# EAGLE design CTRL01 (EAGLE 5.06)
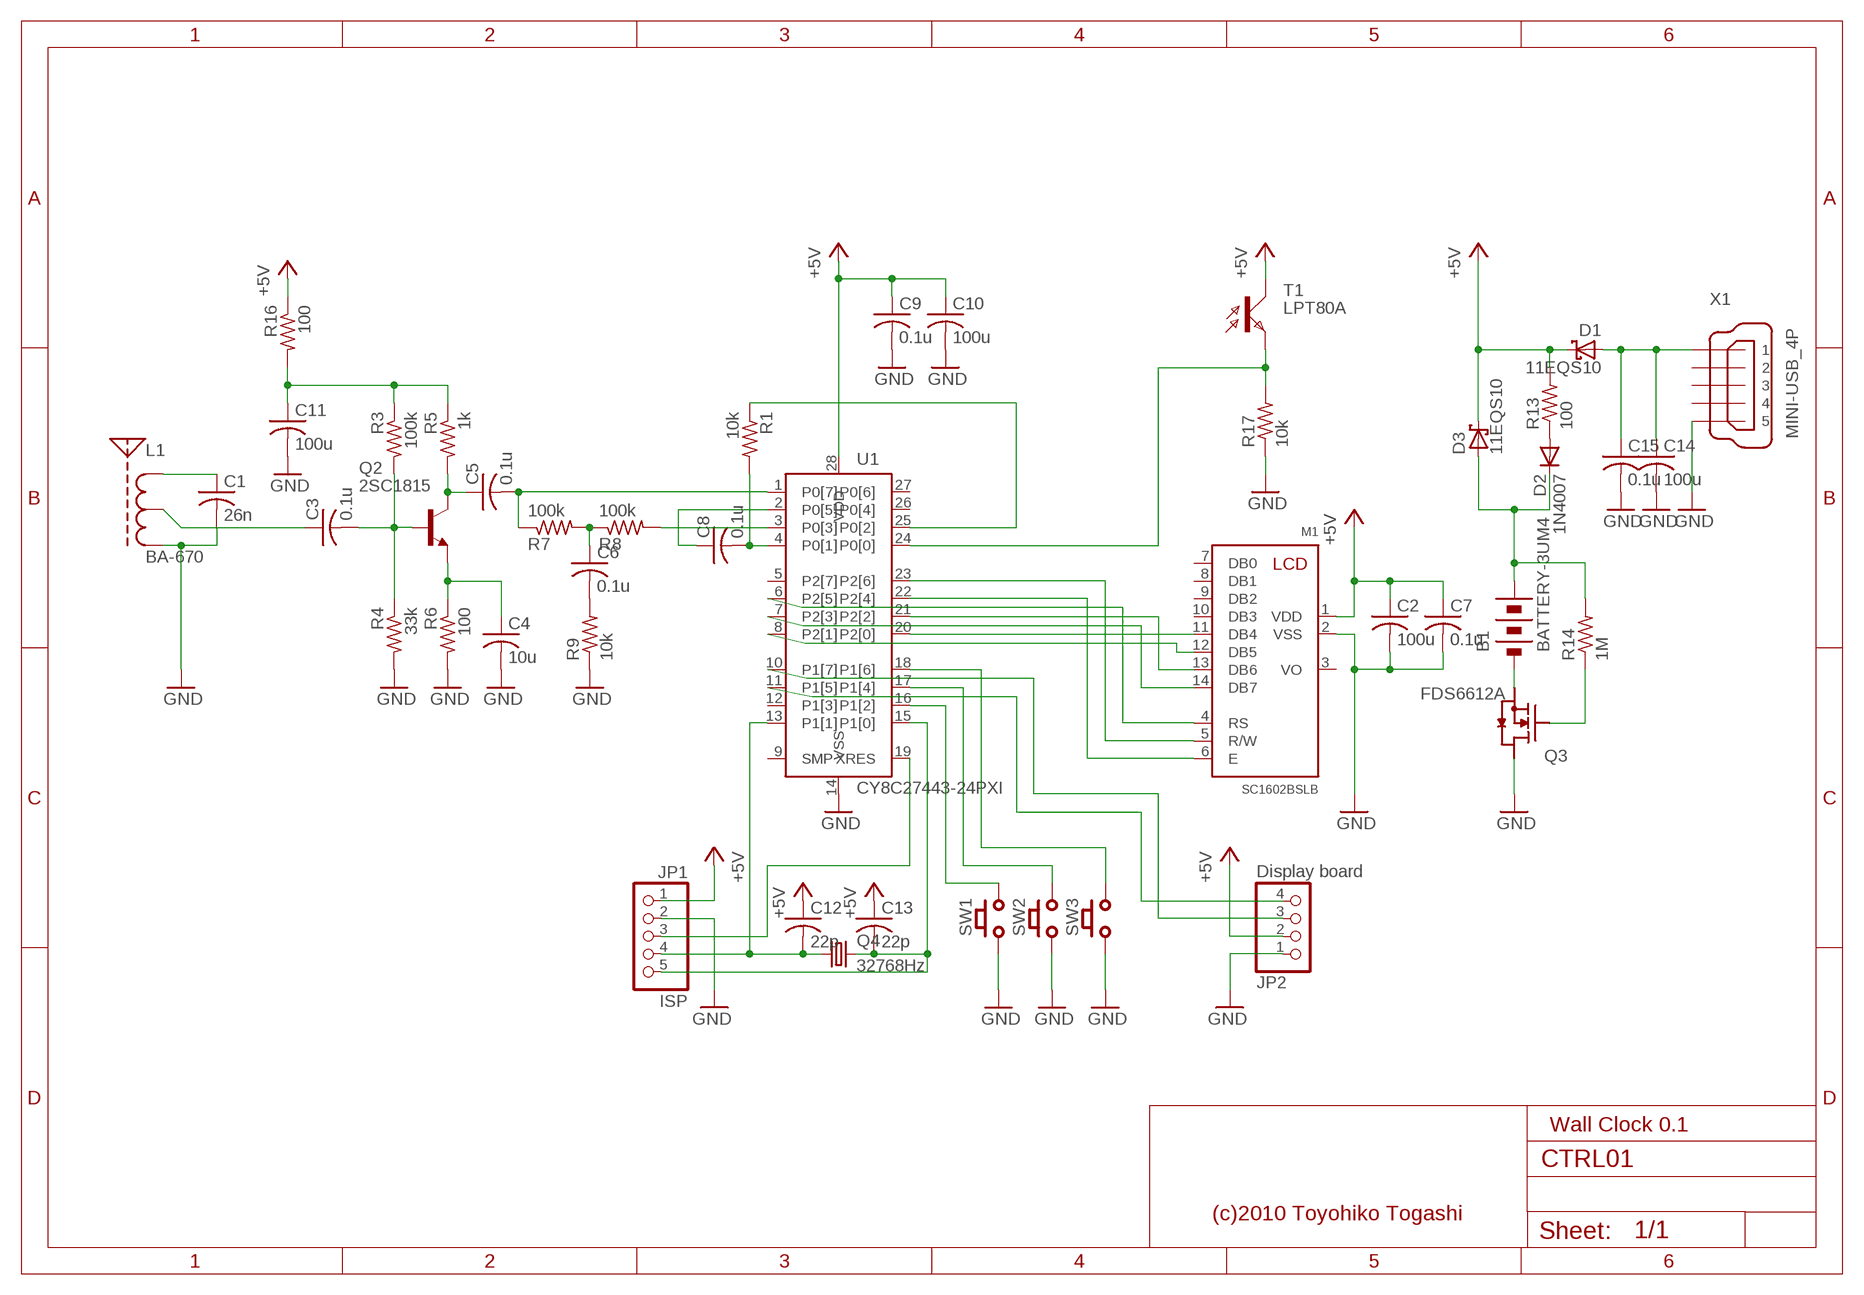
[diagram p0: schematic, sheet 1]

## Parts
B1  BATTERY-3UM4  [BATHLDR-UM4X3]
C1  26n  C-US025-024X044  [C025-024X044]
C2  100u  C-US025-024X044  [C025-024X044]
C3  0.1u  C-US025-024X044  [C025-024X044]
C4  10u  C-US025-024X044  [C025-024X044]
C5  0.1u  C-US050-025X075  [C050-025X075]
C6  0.1u  C-US025-024X044  [C025-024X044]
C7  0.1u  C-US025-024X044  [C025-024X044]
C8  0.1u  C-US025-024X044  [C025-024X044]
C9  0.1u  C-US025-024X044  [C025-024X044]
C10  100u  C-US025-024X044  [C025-024X044]
C11  100u  C-US025-024X044  [C025-024X044]
C12  22p  C-US025-024X044  [C025-024X044]
C13  22p  C-US025-024X044  [C025-024X044]
C14  100u  C-US025-024X044  [C025-024X044]
C15  0.1u  C-US025-024X044  [C025-024X044]
D1  11EQS10  SCHOTTKY-DIODEDO35-7  [DO35-7]
D2  1N4007  1N4148DO35-7  [DO35-7]
D3  11EQS10  SCHOTTKY-DIODEDO35-7  [DO35-7]
JP1  ISP  PINHD-1X5  [1X05]
JP2  Display board  PINHD-1X4  [1X04]
L1  BA-670  [BA-670]
M1  SC1602BSLB  [SC1602B]
Q2  2SC1815  [TO92-ECB]
Q3  FDS6612A  [SOP8]
Q4  32768Hz  CRYSTALTC26H  [TC26H]
R1  10k  R-US_0204/5  [0204/5]
R3  100k  R-US_0204/5  [0204/5]
R4  33k  R-US_0204/5  [0204/5]
R5  1k  R-US_0204/5  [0204/5]
R6  100  R-US_0204/5  [0204/5]
R7  100k  R-US_0204/5  [0204/5]
R8  100k  R-US_0204/5  [0204/5]
R9  10k  R-US_0204/5  [0204/5]
R13  100  R-US_0204/5  [0204/5]
R14  1M  R-US_0204/5  [0204/5]
R16  100  R-US_0204/5  [0204/5]
R17  10k  R-US_0204/5  [0204/5]
SW1  SWITCH-PUSH"  [SWITCH-PUSH]
SW2  SWITCH-PUSH"  [SWITCH-PUSH]
SW3  SWITCH-PUSH"  [SWITCH-PUSH]
T1  LPT80A  [LPT80A]
U1  CY8C27443-24PXI  [DIL28-3]
X1  MINI-USB_4P  AKI-USB-MINI-B  [AKI-USB-MINI-B]

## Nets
+5V: C2.1 C7.1 C9.1 C10.1 C12.1 C13.1 D1.C D3.C JP1.1 JP2.2 M1.1(VDD) R13.2 R16.1 T1.C U1.28(VDD)
N$1: C1.1 L1.NATURAL
N$2: C3.2 Q2.B R3.2 R4.1
N$3: C3.1 L1.BLACK
N$4: R8.2 U1.3(P0[3])
N$5: C4.1 Q2.E R6.1
N$6: C5.1 Q2.C R5.2
N$7: C8.1 U1.2(P0[5])
N$8: JP2.3 U1.10(P1[7])
N$9: C6.1 R7.2 R8.1
N$10: C6.2 R9.2
N$11: C8.2 R1.2 U1.4(P0[1])
N$12: R1.1 U1.25(P0[2])
N$13: C5.2 R7.1 U1.1(P0[7])
N$14: JP2.4 U1.11(P1[5])
N$17: M1.11(DB4) U1.20(P2[0])
N$18: M1.12(DB5) U1.8(P2[1])
N$19: M1.13(DB6) U1.21(P2[2])
N$20: M1.14(DB7) U1.7(P2[3])
N$21: M1.6(E) U1.22(P2[4])
N$22: M1.5(R/W) U1.23(P2[6])
N$23: M1.4(RS) U1.6(P2[5])
N$24: B1.P$2(MINUS) Q3.P$1(S)
N$25: D2.A R13.1
N$27: Q3.P$4(G) R14.1
N$28: B1.P$1(PLUS) D2.C D3.A R14.2
N$30: C11.1 R3.1 R5.1 R16.2
N$31: C12.2 JP1.4 Q4.1 U1.13(P1[1])
N$32: C13.2 JP1.5 Q4.2 U1.15(P1[0])
N$33: SW1.P$2(A2) U1.16(P1[2])
N$34: JP1.3 U1.19(XRES)
N$35: SW2.P$2(A2) U1.17(P1[4])
N$36: SW3.P$2(A2) U1.18(P1[6])
N$37: R17.2 T1.E U1.24(P0[0])
N$38: C14.1 C15.1 D1.A X1.1
N$39: C1.2 C2.2 C4.2 C7.2 C9.2 C10.2 C11.2 C14.2 C15.2 JP1.2 JP2.1 L1.GREEN M1.2(VSS) Q3.P$5(D) R4.2 R6.2 R9.1 R17.1 SW1.P$1(A1) SW2.P$1(A1) SW3.P$1(A1) U1.14(VSS) X1.5 ; supply symbol labelled GND
Unconnected: M1.3(VO) M1.7(DB0) M1.8(DB1) M1.9(DB2) M1.10(DB3) U1.5(P2[7]) U1.12(P1[3]) U1.26(P0[4]) U1.27(P0[6]) X1.2 X1.3 X1.4

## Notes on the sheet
- Wall Clock 0.1
- (c)2010 Toyohiko Togashi

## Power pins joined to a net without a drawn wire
SMP: U1.9(SMP)

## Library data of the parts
B1 = TOG:BATTERY-3: Battery 3cell
C1-C15 = rcl:C-US: CAPACITOR, American symbol
D1 D3 = diode:SCHOTTKY-DIODE: Schottky Diode
D2 = diode:1N4148: DIODE
JP1 = pinhead:PINHD-1X5: PIN HEADER
JP2 = pinhead:PINHD-1X4: PIN HEADER
L1 = TOG:BA-670: AIKO DENSHI MW band AM radio bar antenna 670uH +/-5% Q200~/790kHz 3x8x45mm
M1 = TOG:SC1602BSLB: Character LCD module
Q2 = transistor:2SC1815: NPN EPITAXIAL TRANSISTOR Source: TOSHIBA .. 2SC1815 1.pdf
Q3 = TOG:FDS6612A: N-ch MOS FET
Q4 = crystal:CRYSTAL: CRYSTAL
R1 R3-R9 R13 R14 R16 R17 = rcl:R-US_: RESISTOR, American symbol
SW1-SW3 = TOG:SWITCH-PUSH
T1 = opto-trans-siemens:LPT80A: PHOTO TRANSISTOR
U1 = TOG:CY8C27443: Cypress PSoC Mixe-Signal Array Flash16K,RAM256B, Digital block 8, Analog block 12
X1 = TOG:AKI-USB-MINI-B: Akizuki USB connector MINI-B type

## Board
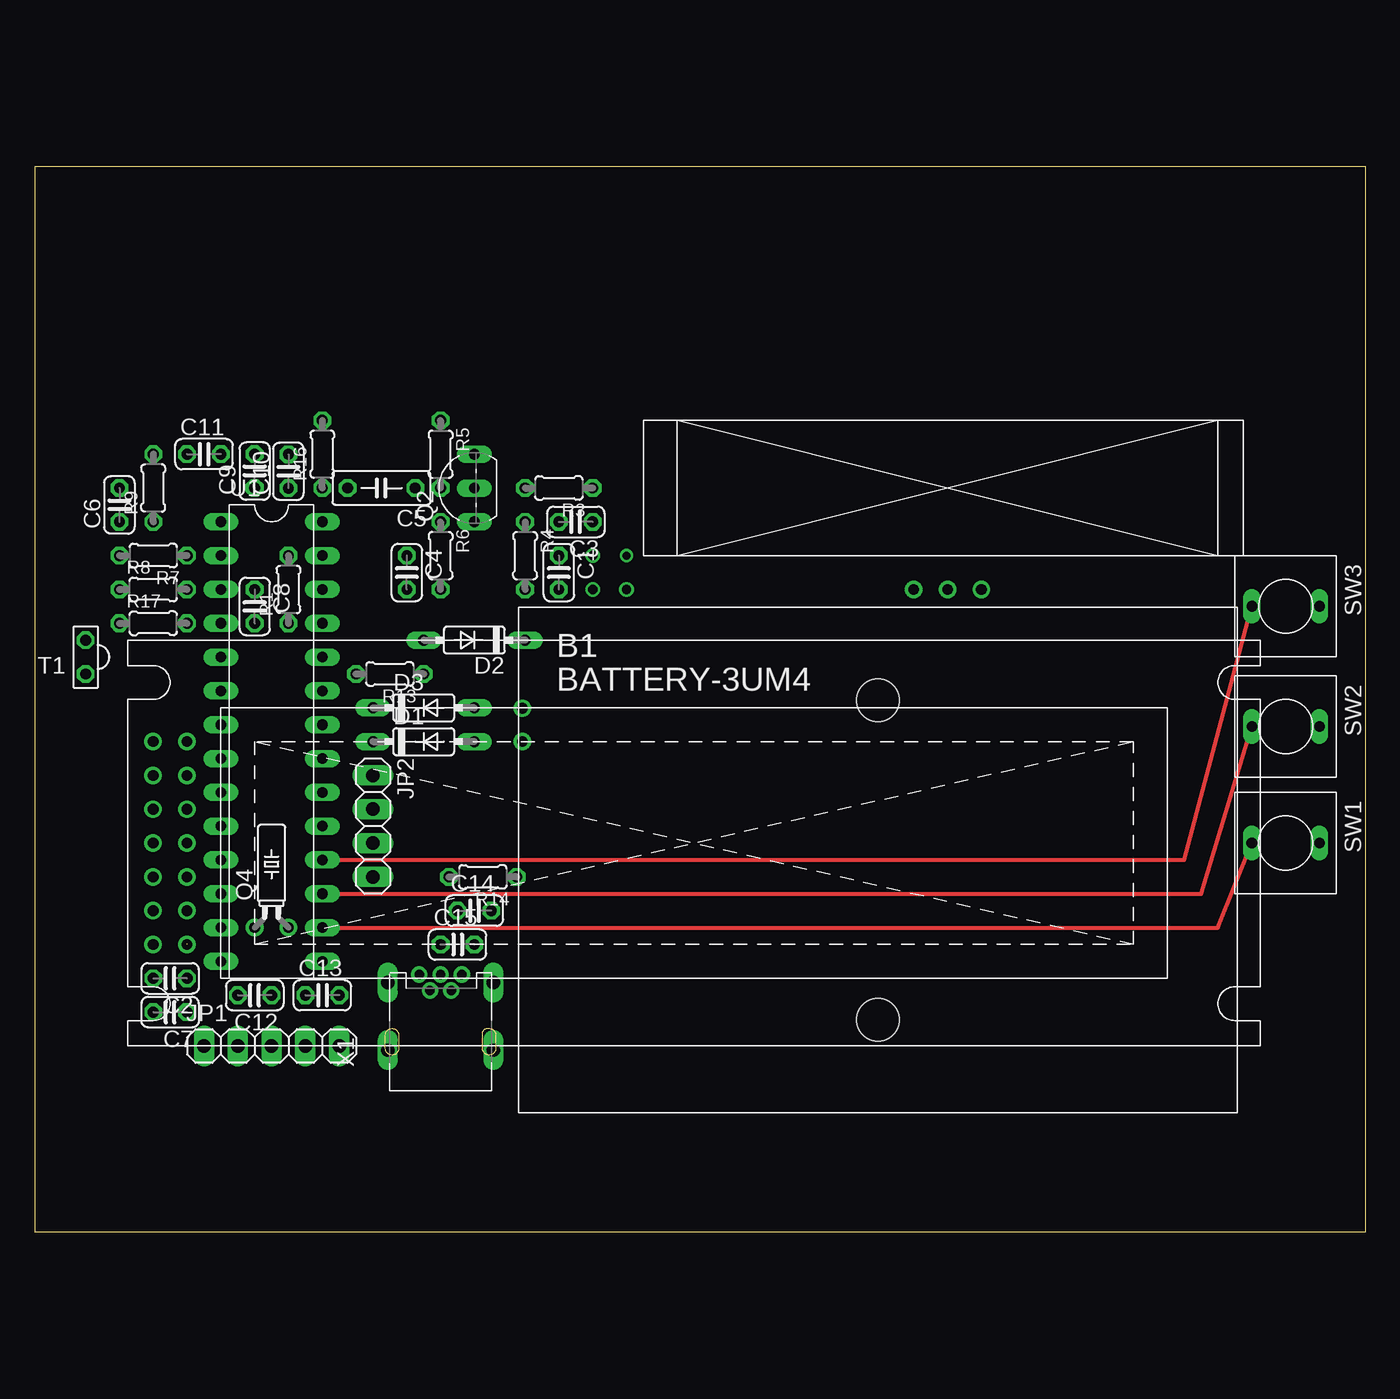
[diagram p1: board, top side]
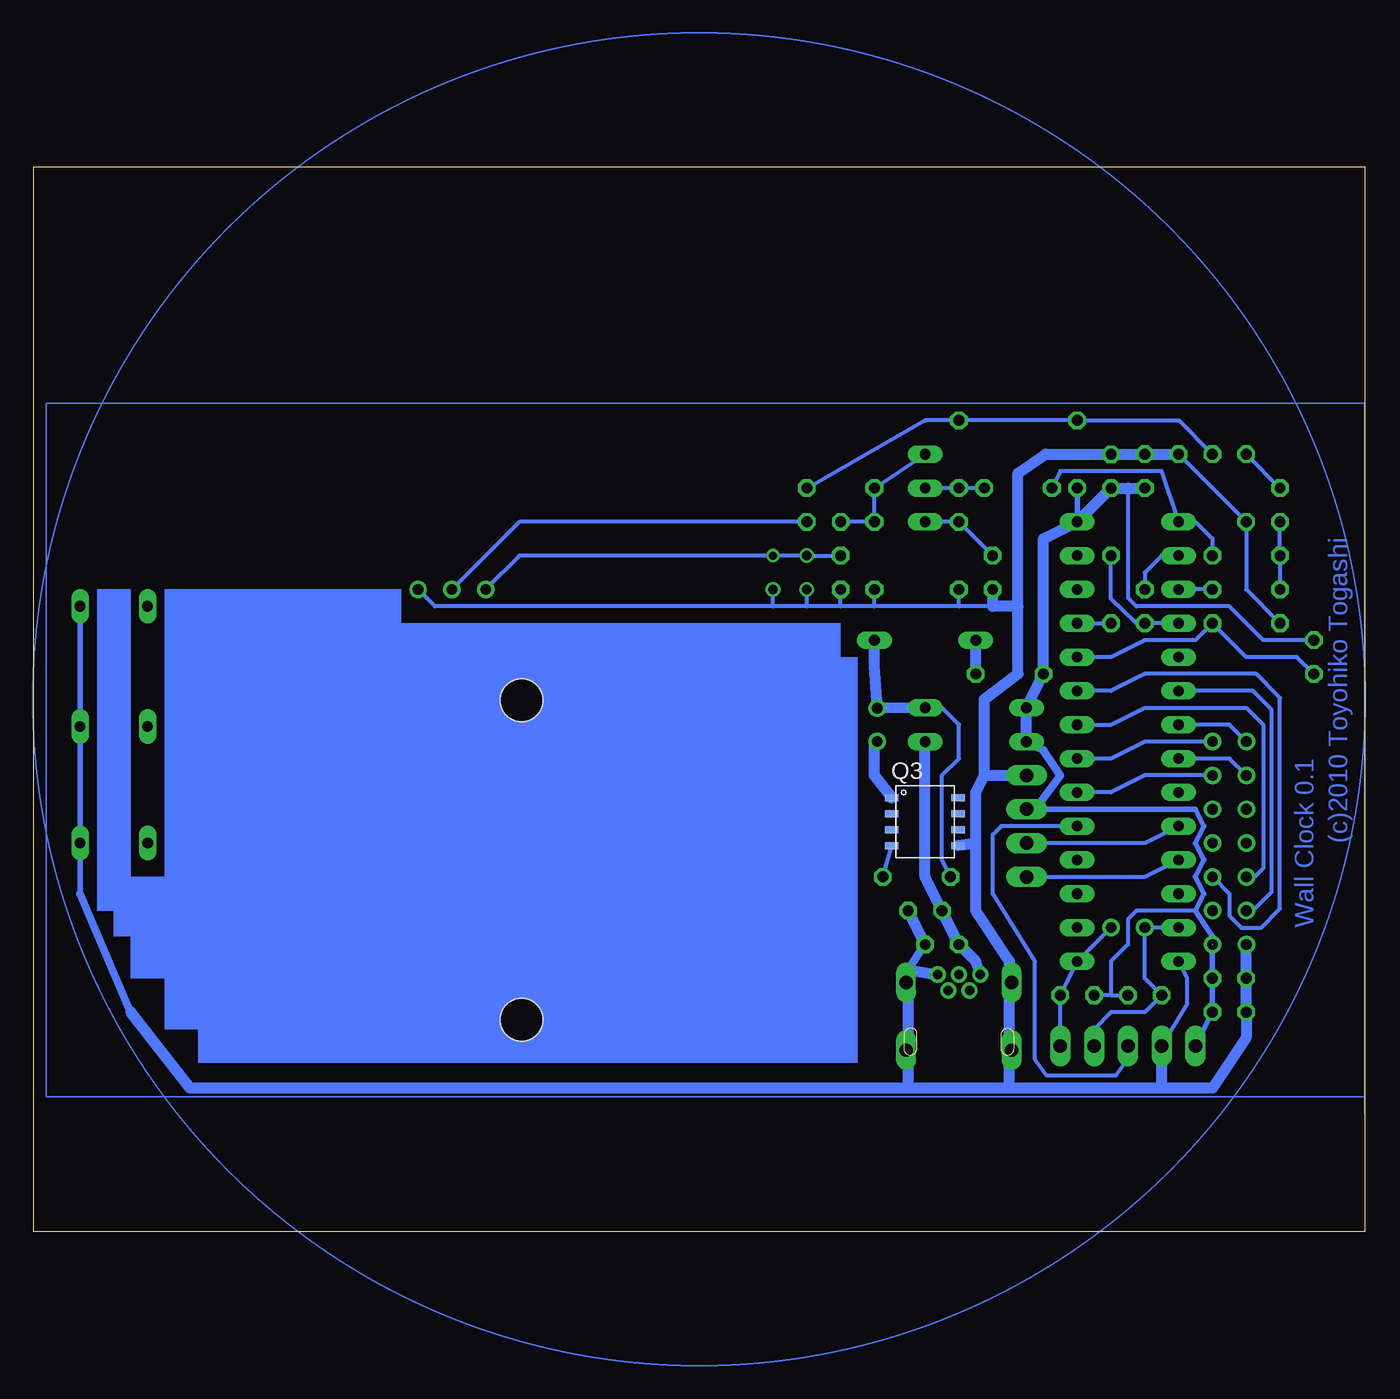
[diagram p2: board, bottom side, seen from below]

Size 100 x 80 mm. Coordinates in mm from the lower left corner, seen from the top.
Outline: 0,0 100,0 100,80 0,80 0,0
Copper layers (1*16): Top 0.035mm / dielectric 1.5mm / Bottom 0.035mm
Design rules "default": minimum track width 10mil, minimum drill 24mil, track to track 8mil, track to pad 8mil, pad to pad 8mil, via to via 8mil, smd to smd 8mil, copper to edge 40mil, drill to drill 8mil, minimum pad ring 10mil, minimum via ring 8mil, stop-mask expansion 4mil, vias tented up to drill 0mil, thermal gap 10mil

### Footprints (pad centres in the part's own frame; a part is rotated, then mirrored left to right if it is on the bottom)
BATHLDR-UM4X3 = drill 0.8 round: P$1 -26.714,11.396; P$2 -26.714,8.888 | hole 3.2: 0,-12; 0,12
C025-024X044 = drill 0.813 octagon: 1 -1.27,0; 2 1.27,0
C050-025X075 = drill 0.813 octagon: 1 -2.54,0; 2 2.54,0
DO35-7 = drill 0.813 long: A 3.81,0; C -3.81,0
1X05 = drill 1.016 long: 1 -5.08,0; 2 -2.54,0; 3 0,0; 4 2.54,0; 5 5.08,0
1X04 = drill 1.016 long: 1 -3.81,0; 2 -1.27,0; 3 1.27,0; 4 3.81,0
BA-670 = drill 0.8 round: BLACK 22.86,-2.54; GREEN 25.4,-2.54; NATURAL 20.32,-2.54
SC1602B = drill 0.8 round: 1 5.08,5.08; 2 2.54,5.08; 3 5.08,7.62; 4 2.54,7.62; 5 5.08,10.16; 6 2.54,10.16; 7 5.08,12.7; 8 2.54,12.7; 9 5.08,15.24; 10 2.54,15.24; 11 5.08,17.78; 12 2.54,17.78; 13 5.08,20.32; 14 2.54,20.32
TO92-ECB = drill 0.813 long: B 2.54,0; C 0,0; E -2.54,0
SOP8 = smd 0.508 x 1.016: P$1 -1.8,-2.5; P$2 -0.6,-2.5; P$3 0.6,-2.5; P$4 1.8,-2.5; P$5 1.8,2.5; P$6 0.6,2.5; P$7 -0.6,2.5; P$8 -1.8,2.5
TC26H = drill 0.813 round: 1 -1.27,0; 2 1.27,0
0204/5 = drill 0.813 octagon: 1 -2.54,0; 2 2.54,0
SWITCH-PUSH = drill 0.8 long: P$1 0,2.54; P$2 0,-2.54
LPT80A = drill 0.813 octagon: C 0,-1.27; E 0,1.27
DIL28-3 = drill 0.8 long: 1 -16.51,-3.81; 2 -13.97,-3.81; 3 -11.43,-3.81; 4 -8.89,-3.81; 5 -6.35,-3.81; 6 -3.81,-3.81; 7 -1.27,-3.81; 8 1.27,-3.81; 9 3.81,-3.81; 10 6.35,-3.81; 11 8.89,-3.81; 12 11.43,-3.81; 13 13.97,-3.81; 14 16.51,-3.81; 15 16.51,3.81; 16 13.97,3.81; 17 11.43,3.81; 18 8.89,3.81; 19 6.35,3.81; 20 3.81,3.81; 21 1.27,3.81; 22 -1.27,3.81; 23 -3.81,3.81; 24 -6.35,3.81; 25 -8.89,3.81; 26 -11.43,3.81; 27 -13.97,3.81; 28 -16.51,3.81
AKI-USB-MINI-B = drill 0.7 pad 1.016 round: 1 2.825,1.6; 2 1.625,0.8; 3 2.825,0; 4 1.625,-0.8; 5 2.825,-1.6 | drill 1 pad 1.422 long: M1 -2.86,3.967; M2 -2.86,-3.967; M3 2.22,3.967; M4 2.22,-3.967

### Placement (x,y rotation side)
B1  63.33,27.94 0 top
C1  39.37,49.53 270 top
C2  10.16,19.05 180 top
C3  40.64,53.34 180 top
C4  27.94,49.53 270 top
C5  26.04,55.88 180 top
C6  6.35,54.61 90 top
C7  10.16,16.51 180 top
C8  16.51,46.99 270 top
C9  16.51,57.15 90 top
C10  19.05,57.14 90 top
C11  12.7,58.42 0 top
C12  16.51,17.78 180 top
C13  21.59,17.78 0 top
C14  33.02,24.13 0 top
C15  31.75,21.59 0 top
D1  29.21,36.83 0 top
D2  33.02,44.45 180 top
D3  29.21,39.37 0 top
JP1  17.78,13.97 0 top
JP2  25.4,30.48 270 top
L1  45.72,50.8 0 top
M1  6.34,16.51 0 top
Q2  33.02,55.88 90 top
Q3  33.02,30.81 270 bottom
Q4  17.78,22.86 0 top
R1  19.05,48.26 90 top
R3  39.37,55.88 180 top
R4  36.83,50.8 270 top
R5  30.48,58.42 270 top
R6  30.48,50.8 270 top
R7  8.89,50.8 180 top
R8  8.89,48.26 0 top
R9  8.89,55.88 90 top
R13  26.67,41.91 180 top
R14  33.66,26.67 180 top
R16  21.59,58.42 90 top
R17  8.89,45.72 0 top
SW1  93.98,29.21 270 top
SW2  93.98,37.96 270 top
SW3  93.99,47 270 top
T1  3.81,43.18 180 top
U1  17.78,36.83 270 top
X1  30.48,16.51 90 top

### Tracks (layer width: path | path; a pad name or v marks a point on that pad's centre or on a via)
+5V  (1 unrouted)
  Bottom 0.305: T1.C 7.62,44.45 10.16,46.99 17.14,46.99 17.78,47.62 17.78,55.87 | 19.05,17.78 C12.1 | 19.05,17.78 19.05,20.32 17.78,21.59 17.78,23.5 17.14,24.13 12.7,24.13 | 19.05,17.78 C13.1
  Bottom 0.406: JP1.1 C7.1 C2.1 M1.1 11.43,22.23 12.7,24.13 12.06,25.4 12.7,26.67 12.06,27.94 12.7,29.21 12.06,30.48 12.7,31.75 24.77,31.75 JP2.2 | U1.28 R16.1
  Bottom 0.61: D1.C 24.13,36.2 22.86,34.29 24.77,31.75
  Bottom 0.813: C9.1 17.78,55.87 C10.1 U1.28 24.13,52.07 R13.2 D3.C D1.C
N$1  (via drill 0.7)
  Bottom 0.305: L1.NATURAL 63.5,50.8 v41.91,50.8 C1.1
N$2
  Bottom 0.305: C3.2 R4.1 R3.2 Q2.B
N$3
  Bottom 0.305: C3.1 63.5,53.34 L1.BLACK
N$4
  Bottom 0.305: R8.2 U1.3
N$5
  Bottom 0.305: Q2.E R6.1 C4.1
N$6
  Bottom 0.305: Q2.C R5.2 C5.1
N$7
  Bottom 0.305: U1.2 15.24,50.8 16.51,49.53 C8.1
N$8
  Bottom 0.305: U1.10 16.51,29.21 JP2.3
N$9
  Bottom 0.305: C6.1 R7.2 R8.1
N$10
  Bottom 0.305: R9.2 C6.2
N$11
  Bottom 0.305: U1.4 C8.2 17.14,45.72 19.05,47.57 R1.2
N$12
  Bottom 0.305: U1.25 R1.1
N$13
  Bottom 0.305: C5.2 22.86,57.15 15.24,57.15 U1.1 12.7,53.34 11.43,52.07 R7.1
N$14
  Bottom 0.305: JP2.4 16.51,26.67 U1.11
N$15  (via drill 0.6)
  other vias: 44.45,50.8
N$17
  Bottom 0.305: M1.11 16.51,34.29 19.05,33.02 U1.20
N$18
  Bottom 0.305: M1.12 10.16,35.56 U1.8
N$19
  Bottom 0.305: M1.13 16.51,36.83 19.05,35.56 U1.21
N$20
  Bottom 0.305: M1.14 10.16,38.1 U1.7
N$21
  Bottom 0.305: U1.22 19.05,38.1 16.51,39.37 8.89,39.37 7.62,38.1 7.62,27.3 8.26,26.67 M1.6
N$22
  Bottom 0.305: M1.5 10.16,25.4 10.16,23.76 9.26,22.86 7.77,22.86 6.35,24.28 6.35,40.11 8.15,41.91 16.51,41.91 19.05,40.64 U1.23
N$23
  Bottom 0.305: M1.4 8.4,24.13 6.99,25.55 6.99,39.22 8.4,40.64 U1.6
N$24
  Bottom 0.813: Q3.P$1 36.83,34.29 36.83,36.83 B1.P$2
N$25
  Bottom 0.813: R13.1 D2.A
N$27
  Bottom 0.305: R14.1 Q3.P$4
N$28
  Bottom 0.305: R14.2 31.75,27.94 31.75,34.29 30.48,35.56 30.48,38.1 31.75,39.37 D3.A
  Bottom 0.813: D2.C 36.83,42.55 B1.P$1 D3.A
N$29
  Bottom 0.127: 0,8.89 0,10.16 | 0,10.16 0,11.43 | 0,10.16 99.06,10.16 99.06,62.23 0,62.23 0,10.16
N$30
  Bottom 0.305: R3.1 33.02,60.96 R5.1 R16.2 13.97,60.96 C11.1
N$31
  Bottom 0.305: U1.13 Q4.1 16.51,19.05 C12.2 16.51,16.51 19.05,16.51 20.32,15.24 JP1.4
N$32
  Bottom 0.305: Q4.2 U1.15 C13.2 JP1.5
N$33
  Top 0.305: U1.16 88.9,22.86 SW1.P$2
N$34
  Bottom 0.305: JP1.3 17.78,12.96 18.68,11.75 23.87,11.75 24.77,12.96 24.77,20.32 27.94,25.4 27.94,29.84 27.3,30.48 U1.19
N$35
  Top 0.305: U1.17 87.63,25.4 SW2.P$2
N$36
  Top 0.305: U1.18 86.36,27.94 SW3.P$2
N$37
  Bottom 0.305: U1.24 19.05,43.18 16.51,44.45 12.7,44.45 R17.2 8.89,43.18 5.08,43.18 T1.E
N$38
  Bottom 0.813: X1.1 29.21,20.32 C15.1 C14.1 33.02,26.67 D1.A
N$39  (via drill 0.7)
  Bottom 0.305: L1.GREEN 69.85,46.99 44.45,46.99 | 30.48,46.99 36.83,46.99 | 36.83,46.99 R4.2 | 30.48,46.99 R6.2 | C11.2 R9.1 8.89,48.26 R17.1 | 27.94,46.99 30.48,46.99 | 36.83,46.99 39.37,46.99 | 39.37,46.99 41.91,46.99 | 41.91,46.99 44.45,46.99 | 39.37,46.99 C1.2 | 41.91,46.99 v41.91,48.26 | 44.45,46.99 v44.45,48.26 | JP1.2 13.34,17.14 13.34,19.05 U1.14
  Bottom 0.406: SW3.P$1 SW2.P$1 SW1.P$1 96.52,25.4
  Bottom 0.61: 92.71,16.51 96.52,25.4 | 34.29,19.68 C15.2
  Bottom 0.813: 15.24,10.79 11.43,10.79 8.89,14.61 C7.2 C2.2 M1.2 | 15.24,10.79 JP1.2 | 28.57,34.29 JP2.1 | C11.2 C9.2 C10.2 23.98,58.42 26.04,57 26.04,46.99 | 28.57,34.29 28.57,40.01 26.04,41.91 26.04,46.99 | 26.67,10.79 34.29,10.79 | 34.29,10.79 88.27,10.79 92.71,16.51 | 15.24,10.79 26.67,10.79 | 26.04,46.99 27.94,46.99 C4.2 | 29.21,29.21 29.21,33.02 28.57,34.29 | 29.21,29.21 29.21,24.13 26.67,20.32 26.67,10.79 | 34.29,10.79 34.29,19.68 X1.5 | C15.2 C14.2 | 29.21,29.21 Q3.P$5
(copper drawn outside any net)
  shapes: Bottom area x7, Bottom circle x1

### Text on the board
Bottom: (c)2010 Toyohiko Togashi | Wall Clock 0.1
